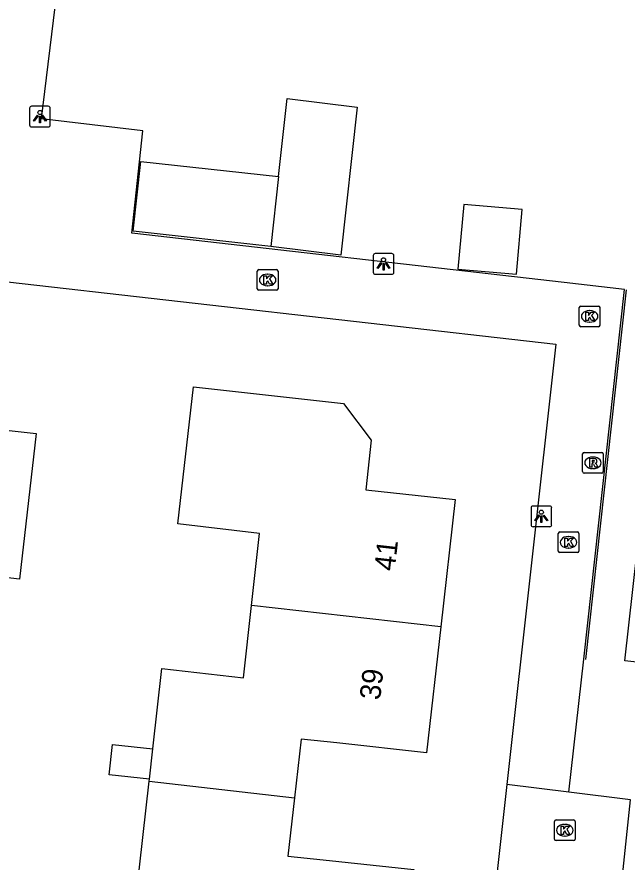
# Model space of a CAD drawing. Extents: x 162082 to 163393, y 388091 to 388632.
# Drawn here: x 162880.67 to 162910.17, y 388261.2 to 388302.07 of the extents above; entities that cross this region are included whole.
import ezdxf

# ---------------------------------------------------------------- set-up
doc = ezdxf.new("R2010")
doc.units = 0
for name, color, linetype in [('IMGEO_Kolk', 7, 'Continuous'), ('IMGEO_Lichtpunt', 7, 'Continuous'), ('IMGEO_Muur', 7, 'Continuous'), ('IMGEO_Pand', 7, 'Continuous'), ('IMGEO_Pand_nummerreeks', 7, 'Continuous'), ('IMGEO_Rioolput', 7, 'Continuous'), ('IMGEO_Voetpad_open', 7, 'Continuous')]:
    doc.layers.add(name, color=color, linetype=linetype)

msp = doc.modelspace()

# ---------------------------------------------------------------- linework, layer by layer
at = {"layer": 'IMGEO_Kolk'}
for p, q in [((162892.293, 388288.924), (162892.293, 388289.776)), ((162892.368, 388289.85), (162893.22, 388289.85)), ((162892.781, 388289.63), (162892.806, 388289.63)), ((162893.294, 388289.776), (162893.294, 388288.924)), ((162893.22, 388288.85), (162892.368, 388288.85)), ((162892.804, 388289.07), (162892.779, 388289.07)), ((162907.861, 388287.164), (162907.861, 388288.016)), ((162907.936, 388288.09), (162908.788, 388288.09)), ((162908.862, 388288.016), (162908.862, 388287.164)), ((162908.349, 388287.87), (162908.374, 388287.87)), ((162908.372, 388287.31), (162908.347, 388287.31)), ((162908.788, 388287.09), (162907.936, 388287.09)), ((162906.841, 388276.24), (162906.841, 388277.092)), ((162906.916, 388277.166), (162907.768, 388277.166)), ((162907.329, 388276.946), (162907.354, 388276.946)), ((162907.842, 388277.092), (162907.842, 388276.24)), ((162907.768, 388276.166), (162906.916, 388276.166)), ((162907.352, 388276.386), (162907.327, 388276.386)), ((162906.66, 388262.318), (162906.66, 388263.17)), ((162906.735, 388263.244), (162907.587, 388263.244)), ((162907.148, 388263.024), (162907.173, 388263.024)), ((162907.661, 388263.17), (162907.661, 388262.318)), ((162907.587, 388262.244), (162906.735, 388262.244)), ((162907.171, 388262.464), (162907.146, 388262.464))]:
    msp.add_line(p, q, dxfattribs=at)
for points in [[(162892.293, 388288.924), (162892.293, 388289.776)], [(162892.368, 388289.85), (162893.22, 388289.85)], [(162893.294, 388289.776), (162893.294, 388288.924)], [(162892.614, 388289.55), (162892.737, 388289.55), (162892.737, 388289.399), (162892.867, 388289.55), (162893.031, 388289.55), (162892.885, 388289.399), (162893.038, 388289.15), (162892.886, 388289.15), (162892.801, 388289.314), (162892.737, 388289.247), (162892.737, 388289.15), (162892.614, 388289.15), (162892.614, 388289.55)], [(162893.22, 388288.85), (162892.368, 388288.85)], [(162907.861, 388287.164), (162907.861, 388288.016)], [(162907.936, 388288.09), (162908.788, 388288.09)], [(162908.862, 388288.016), (162908.862, 388287.164)], [(162908.182, 388287.79), (162908.305, 388287.79), (162908.305, 388287.639), (162908.435, 388287.79), (162908.599, 388287.79), (162908.453, 388287.639), (162908.606, 388287.39), (162908.454, 388287.39), (162908.369, 388287.554), (162908.305, 388287.487), (162908.305, 388287.39), (162908.182, 388287.39), (162908.182, 388287.79)], [(162908.788, 388287.09), (162907.936, 388287.09)], [(162906.841, 388276.24), (162906.841, 388277.092)], [(162906.916, 388277.166), (162907.768, 388277.166)], [(162907.842, 388277.092), (162907.842, 388276.24)], [(162907.162, 388276.866), (162907.285, 388276.866), (162907.285, 388276.715), (162907.415, 388276.866), (162907.579, 388276.866), (162907.433, 388276.715), (162907.586, 388276.466), (162907.434, 388276.466), (162907.349, 388276.63), (162907.285, 388276.563), (162907.285, 388276.466), (162907.162, 388276.466), (162907.162, 388276.866)], [(162907.768, 388276.166), (162906.916, 388276.166)], [(162906.66, 388262.318), (162906.66, 388263.17)], [(162906.735, 388263.244), (162907.587, 388263.244)], [(162907.661, 388263.17), (162907.661, 388262.318)], [(162906.981, 388262.944), (162907.104, 388262.944), (162907.104, 388262.793), (162907.234, 388262.944), (162907.398, 388262.944), (162907.252, 388262.793), (162907.405, 388262.544), (162907.253, 388262.544), (162907.168, 388262.708), (162907.104, 388262.641), (162907.104, 388262.544), (162906.981, 388262.544), (162906.981, 388262.944)], [(162907.587, 388262.244), (162906.735, 388262.244)]]:
    msp.add_lwpolyline(points, dxfattribs=at)
for centre, start, end in [((162892.37, 388289.774), 91.552, 178.448), ((162892.37, 388289.774), 91.552, 178.448), ((162893.218, 388289.774), 1.552, 88.448), ((162893.218, 388289.774), 1.552, 88.448), ((162892.37, 388288.926), 181.552, 268.448), ((162892.37, 388288.926), 181.552, 268.448), ((162893.218, 388288.926), 271.552, 358.448), ((162893.218, 388288.926), 271.552, 358.448), ((162907.938, 388288.014), 91.552, 178.448), ((162907.938, 388288.014), 91.552, 178.448), ((162908.786, 388288.014), 1.552, 88.448), ((162908.786, 388288.014), 1.552, 88.448), ((162907.938, 388287.166), 181.552, 268.448), ((162907.938, 388287.166), 181.552, 268.448), ((162908.786, 388287.166), 271.552, 358.448), ((162908.786, 388287.166), 271.552, 358.448), ((162906.918, 388277.09), 91.552, 178.448), ((162906.918, 388277.09), 91.552, 178.448), ((162907.766, 388277.09), 1.552, 88.448), ((162907.766, 388277.09), 1.552, 88.448), ((162906.918, 388276.242), 181.552, 268.448), ((162906.918, 388276.242), 181.552, 268.448), ((162907.766, 388276.242), 271.552, 358.448), ((162907.766, 388276.242), 271.552, 358.448), ((162906.737, 388263.168), 91.552, 178.448), ((162906.737, 388263.168), 91.552, 178.448), ((162907.585, 388263.168), 1.552, 88.448), ((162907.585, 388263.168), 1.552, 88.448), ((162906.737, 388262.32), 181.552, 268.448), ((162906.737, 388262.32), 181.552, 268.448), ((162907.585, 388262.32), 271.552, 358.448), ((162907.585, 388262.32), 271.552, 358.448)]:
    msp.add_arc(centre, 0.0765, start, end, dxfattribs=at)
for centre, major_axis, ratio, start_param, end_param in [((162892.78, 388289.35), (-0.387, 0.002), 0.722429, 4.712389, 7.853982), ((162892.805, 388289.35), (-0.39, 0.002), 0.717154, 1.570796, 4.712389), ((162908.348, 388287.59), (-0.387, 0.002), 0.722429, 4.712389, 7.853982), ((162908.373, 388287.59), (-0.39, 0.002), 0.717154, 1.570796, 4.712389), ((162907.328, 388276.666), (-0.387, 0.002), 0.722429, 4.712389, 7.853982), ((162907.353, 388276.666), (-0.39, 0.002), 0.717154, 1.570796, 4.712389), ((162907.147, 388262.744), (-0.387, 0.002), 0.722429, 4.712389, 7.853982), ((162907.172, 388262.744), (-0.39, 0.002), 0.717154, 1.570796, 4.712389)]:
    msp.add_ellipse(centre, major_axis=major_axis, ratio=ratio, start_param=start_param, end_param=end_param, dxfattribs=at)
at = {"layer": 'IMGEO_Lichtpunt'}
for p, q in [((162882.186, 388297.747), (162881.378, 388297.747)), ((162882.186, 388297.747), (162881.378, 388297.747)), ((162881.284, 388297.652), (162881.284, 388296.845)), ((162881.284, 388297.652), (162881.284, 388296.845)), ((162882.28, 388296.845), (162882.28, 388297.652)), ((162882.28, 388296.845), (162882.28, 388297.652)), ((162881.378, 388296.751), (162882.186, 388296.751)), ((162881.378, 388296.751), (162882.186, 388296.751)), ((162897.897, 388290.528), (162897.897, 388289.721)), ((162897.897, 388290.528), (162897.897, 388289.721)), ((162898.799, 388290.623), (162897.991, 388290.623)), ((162898.799, 388290.623), (162897.991, 388290.623)), ((162898.893, 388289.721), (162898.893, 388290.528)), ((162898.893, 388289.721), (162898.893, 388290.528)), ((162897.991, 388289.627), (162898.799, 388289.627)), ((162897.991, 388289.627), (162898.799, 388289.627)), ((162905.529, 388278.323), (162905.529, 388277.516)), ((162905.529, 388278.323), (162905.529, 388277.516)), ((162906.431, 388278.418), (162905.623, 388278.418)), ((162906.431, 388278.418), (162905.623, 388278.418)), ((162906.525, 388277.516), (162906.525, 388278.323)), ((162906.525, 388277.516), (162906.525, 388278.323)), ((162905.623, 388277.422), (162906.431, 388277.422)), ((162905.623, 388277.422), (162906.431, 388277.422))]:
    msp.add_line(p, q, dxfattribs=at)
for points in [[(162881.658, 388297.316), (162881.697, 388297.288), (162881.509, 388297.026), (162881.471, 388297.053), (162881.658, 388297.316)], [(162881.76, 388297.268), (162881.807, 388297.268), (162881.807, 388296.946), (162881.76, 388296.946), (162881.76, 388297.268)], [(162881.87, 388297.288), (162881.908, 388297.315), (162882.095, 388297.053), (162882.056, 388297.025), (162881.87, 388297.288)], [(162898.271, 388290.192), (162898.31, 388290.164), (162898.122, 388289.902), (162898.084, 388289.929), (162898.271, 388290.192)], [(162898.373, 388290.144), (162898.42, 388290.144), (162898.42, 388289.822), (162898.373, 388289.822), (162898.373, 388290.144)], [(162898.483, 388290.164), (162898.521, 388290.191), (162898.708, 388289.929), (162898.669, 388289.901), (162898.483, 388290.164)], [(162905.903, 388277.987), (162905.942, 388277.959), (162905.754, 388277.697), (162905.716, 388277.724), (162905.903, 388277.987)], [(162906.005, 388277.939), (162906.052, 388277.939), (162906.052, 388277.617), (162906.005, 388277.617), (162906.005, 388277.939)], [(162906.115, 388277.959), (162906.153, 388277.986), (162906.34, 388277.724), (162906.301, 388277.696), (162906.115, 388277.959)]]:
    msp.add_lwpolyline(points, dxfattribs=at)
for centre in [(162881.783, 388297.45), (162898.396, 388290.326), (162906.028, 388278.121)]:
    msp.add_circle(centre, 0.0994, dxfattribs=at)
for centre, start, end in [((162881.378, 388297.652), 90, 180), ((162881.378, 388297.652), 90, 180), ((162882.186, 388297.652), 0, 90), ((162882.186, 388297.652), 0, 90), ((162881.378, 388296.845), 180, 270), ((162881.378, 388296.845), 180, 270), ((162882.186, 388296.845), 270, 0), ((162882.186, 388296.845), 270, 360), ((162897.991, 388290.528), 90, 180), ((162897.991, 388290.528), 90, 180), ((162898.799, 388290.528), 0, 90), ((162898.799, 388290.528), 0, 90), ((162897.991, 388289.721), 180, 270), ((162897.991, 388289.721), 180, 270), ((162898.799, 388289.721), 270, 0), ((162898.799, 388289.721), 270, 360), ((162905.623, 388278.323), 90, 180), ((162905.623, 388278.323), 90, 180), ((162906.431, 388278.323), 0, 90), ((162906.431, 388278.323), 0, 90), ((162905.623, 388277.516), 180, 270), ((162905.623, 388277.516), 180, 270), ((162906.431, 388277.516), 270, 0), ((162906.431, 388277.516), 270, 360)]:
    msp.add_arc(centre, 0.0946, start, end, dxfattribs=at)
at = {"layer": 'IMGEO_Muur'}
msp.add_lwpolyline([(162908.181, 388271.003), (162910.148, 388288.869)], dxfattribs=at)
at = {"layer": 'IMGEO_Pand'}
for points in [[(162893.325, 388294.349), (162893.742, 388298.123), (162897.125, 388297.712), (162896.338, 388290.55), (162892.951, 388290.969)], [(162892.951, 388290.969), (162886.291, 388291.707), (162886.666, 388295.086), (162893.325, 388294.349)], [(162893.325, 388294.349), (162892.951, 388290.969)], [(162901.992, 388289.878), (162904.818, 388289.625), (162905.098, 388292.751), (162902.272, 388293.004), (162901.992, 388289.878)], [(162892.016, 388273.616), (162892.405, 388277.093), (162888.45, 388277.552), (162889.202, 388284.18), (162896.462, 388283.381), (162897.805, 388281.603), (162897.54, 388279.207), (162901.863, 388278.731), (162901.167, 388272.579)], [(162878.68, 388282.253), (162881.606, 388281.919), (162880.794, 388274.887), (162877.89, 388275.216)], [(162918.647, 388263.856), (162912.47, 388264.539), (162912.915, 388268.89), (162913.089, 388270.596), (162910.061, 388270.934), (162910.851, 388277.975), (162916.54, 388277.317), (162916.09, 388273.372), (162919.583, 388272.995)], [(162887.239, 388266.673), (162887.671, 388270.558), (162891.625, 388270.117), (162892.016, 388273.616)], [(162901.167, 388272.579), (162892.016, 388273.616)], [(162901.167, 388272.579), (162900.478, 388266.489), (162896.137, 388266.965), (162894.413, 388267.154), (162894.091, 388264.312)], [(162887.076, 388265.211), (162885.129, 388265.428), (162885.292, 388266.889), (162887.239, 388266.673)], [(162887.076, 388265.211), (162887.239, 388266.673)], [(162890.014, 388255.721), (162890.404, 388259.182), (162886.459, 388259.669), (162887.066, 388265.122)], [(162887.066, 388265.122), (162887.076, 388265.211)], [(162887.066, 388265.122), (162894.091, 388264.312)], [(162894.091, 388264.312), (162893.772, 388261.491), (162895.48, 388261.31), (162899.855, 388260.845), (162899.145, 388254.66)]]:
    msp.add_lwpolyline(points, dxfattribs=at)
at = {"layer": 'IMGEO_Rioolput'}
for p, q in [((162908.096, 388281.01), (162908.948, 388281.01)), ((162908.021, 388280.084), (162908.021, 388280.936)), ((162908.509, 388280.79), (162908.534, 388280.79)), ((162909.022, 388280.936), (162909.022, 388280.084)), ((162908.532, 388280.23), (162908.507, 388280.23)), ((162908.948, 388280.01), (162908.096, 388280.01))]:
    msp.add_line(p, q, dxfattribs=at)
for points in [[(162908.096, 388281.01), (162908.948, 388281.01)], [(162908.021, 388280.084), (162908.021, 388280.936)], [(162908.61, 388280.708), (162908.358, 388280.71), (162908.358, 388280.31)], [(162908.536, 388280.629), (162908.482, 388280.629), (162908.482, 388280.548)], [(162909.022, 388280.936), (162909.022, 388280.084)], [(162908.358, 388280.31), (162908.482, 388280.31), (162908.482, 388280.472), (162908.493, 388280.472)], [(162908.482, 388280.548), (162908.534, 388280.548)], [(162908.54, 388280.443), (162908.611, 388280.31), (162908.751, 388280.31), (162908.686, 388280.436)], [(162908.948, 388280.01), (162908.096, 388280.01)]]:
    msp.add_lwpolyline(points, dxfattribs=at)
for centre, radius, start, end in [((162908.098, 388280.934), 0.0765, 91.552, 178.448), ((162908.098, 388280.934), 0.0765, 91.552, 178.448), ((162908.946, 388280.934), 0.0765, 1.552, 88.448), ((162908.946, 388280.934), 0.0765, 1.552, 88.448), ((162908.542, 388280.533), 0.0964, 77.0061, 93.1865), ((162908.556, 388280.59), 0.0378, 276.6634, 79.6772), ((162908.609, 388280.598), 0.109, 350.3612, 89.416), ((162908.607, 388280.598), 0.112, 277.5842, 350.9817), ((162908.492, 388280.419), 0.0533, 26.0293, 88.6989), ((162908.518, 388280.737), 0.19, 274.7715, 282.9687), ((162908.591, 388280.383), 0.108, 29.5134, 73.7905), ((162908.098, 388280.086), 0.0765, 181.552, 268.448), ((162908.098, 388280.086), 0.0765, 181.552, 268.448), ((162908.946, 388280.086), 0.0765, 271.552, 358.448), ((162908.946, 388280.086), 0.0765, 271.552, 358.448)]:
    msp.add_arc(centre, radius, start, end, dxfattribs=at)
for centre, major_axis, ratio, start_param, end_param in [((162908.508, 388280.51), (-0.387, 0.002), 0.722429, 4.712389, 7.853982), ((162908.533, 388280.51), (-0.39, 0.002), 0.717154, 1.570796, 4.712389)]:
    msp.add_ellipse(centre, major_axis=major_axis, ratio=ratio, start_param=start_param, end_param=end_param, dxfattribs=at)
at = {"layer": 'IMGEO_Voetpad_open'}
for points in [[(162907.36, 388264.58), (162908.073, 388271.01), (162910.054, 388288.891), (162907.123, 388289.226), (162886.23, 388291.615), (162886.758, 388296.567), (162881.865, 388297.138), (162882.593, 388303.237)], [(162879.495, 388289.345), (162906.732, 388286.253), (162904.351, 388264.947)], [(162904.351, 388264.947), (162902.692, 388250), (162902.18, 388245.39), (162907.176, 388244.804), (162903.186, 388209.857)], [(162907.36, 388264.58), (162904.351, 388264.947)], [(162951.024, 388262.43), (162923.899, 388256.008), (162923.853, 388256.162), (162924.044, 388257.709), (162909.814, 388259.308), (162910.334, 388264.217), (162907.36, 388264.58)]]:
    msp.add_lwpolyline(points, dxfattribs=at)

# ---------------------------------------------------------------- texts
at = {"layer": 'IMGEO_Pand_nummerreeks'}
for s, rotation, p in [('41', 83.5453, (162898.932, 388275.246)), ('39', 83.543, (162898.228, 388269.012))]:
    msp.add_text(s, height=1, rotation=rotation, dxfattribs=at).set_placement(p)

doc.saveas('drawing.dxf')
